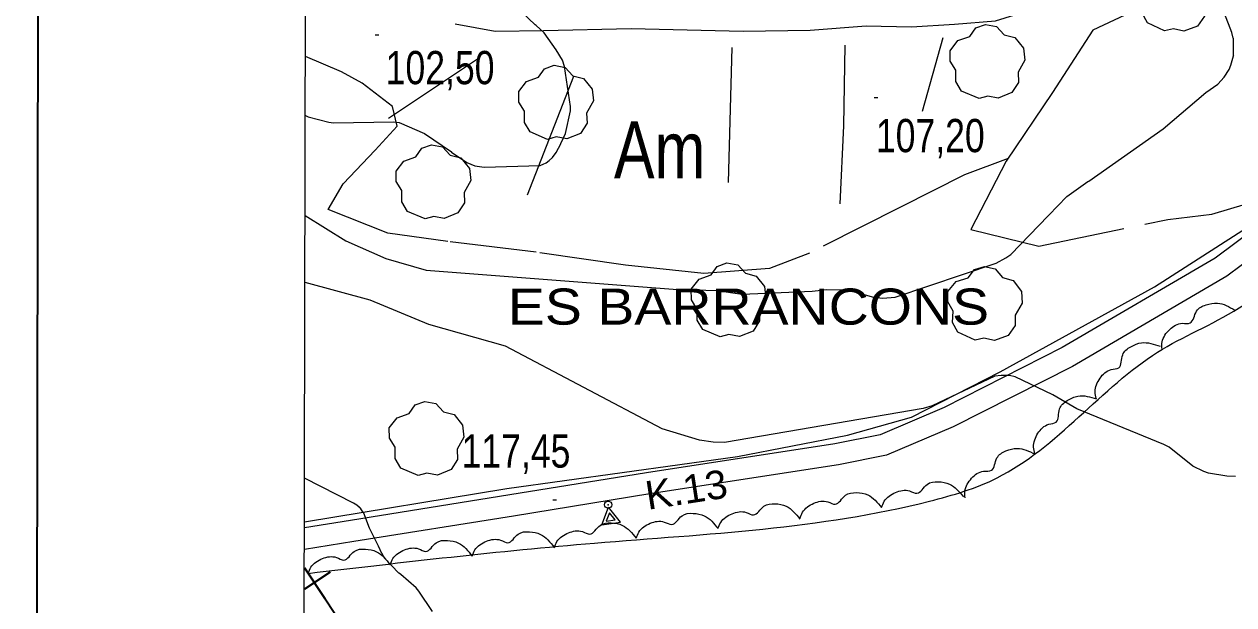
# Model space of a CAD drawing. Extents: x 483843 to 488449, y 4381269 to 4384483.
# Drawn here: x 484025.5 to 484343.7, y 4383510 to 4383662.8 of the extents above; entities that cross this region are included whole.
import ezdxf
from ezdxf.enums import TextEntityAlignment as Align

# ---------------------------------------------------------------- set-up
doc = ezdxf.new("R2010")
doc.units = 0
doc.header["$LTSCALE"] = 3.8
doc.header["$PDMODE"] = 32
doc.header["$PDSIZE"] = 1.9
doc.linetypes.add('LONG_DASHED', pattern=[7.5, 6, -1.5])
for name, color, linetype, lineweight in [('1', 7, 'Continuous', 13), ('25', 7, 'LONG_DASHED', 25), ('27', 7, 'Continuous', 25), ('29', 7, 'Continuous', 13), ('34', 7, 'Continuous', 35), ('36', 7, 'Continuous', 25), ('38', 7, 'Continuous', 25), ('41', 7, 'Continuous', 13), ('51', 7, 'Continuous', 13), ('7', 7, 'Continuous', 13), ('9', 7, 'Continuous', 13)]:
    doc.layers.add(name, color=color, linetype=linetype, lineweight=lineweight)
doc.layers.add('31', color=7, linetype='Continuous')
doc.layers.add('5', color=7, linetype='Continuous')

msp = doc.modelspace()

# ---------------------------------------------------------------- linework, layer by layer
at = {"layer": '1', "lineweight": 35}
msp.add_lwpolyline([(484030.2, 4384207.38), (487748.7, 4384200.21), (487743.96, 4381745.22), (484025.46, 4381752.39)], close=True, dxfattribs=at)
at = {"layer": '1'}
msp.add_lwpolyline([(484100.5, 4384135.8), (487678, 4384129), (487674.1, 4381816.7), (484095.6, 4381823.6)], close=True, dxfattribs=at)
at = {"layer": '25'}
for points in [[(484274.54, 4383608.75), (484292.45, 4383604.39), (484326.41, 4383611.41), (484337.99, 4383612.75), (484347.07, 4383615.48), (484354, 4383620.65), (484359.61, 4383632.36), (484364.31, 4383647.45), (484367.45, 4383659.95), (484366.16, 4383665.4), (484359.29, 4383669.31), (484346.08, 4383669.6), (484334.83, 4383667.88), (484324.29, 4383666.16), (484315.1, 4383665.12), (484306.65, 4383661.22)], [(484284.35, 4383627.47), (484272.84, 4383623.15), (484256.06, 4383614.67), (484232.1, 4383602.56), (484221.61, 4383598.5), (484204.26, 4383597.15), (484183.7, 4383599.37), (484160.17, 4383602.77), (484136.93, 4383605.6), (484121.15, 4383607.8), (484105.46, 4383613.98), (484109.42, 4383620.81), (484117.79, 4383629.65), (484123.6, 4383635.9), (484122.4, 4383641.14), (484114.42, 4383647.28), (484108.94, 4383650.21), (484099.48, 4383654.25)]]:
    msp.add_lwpolyline(points, dxfattribs=at)
at = {"layer": '27'}
for points in [[(484100.18, 4383518.27), (484175.5, 4383526.23), (484263.69, 4383537.26), (484281.44, 4383543.39), (484323.7, 4383576.47), (484345.13, 4383588.11), (484350.64, 4383590.56), (484356.77, 4383588.11), (484365.95, 4383583.21), (484390.45, 4383569.12), (484418, 4383565.44), (484471.89, 4383563.61), (484483.53, 4383561.15), (484486.59, 4383558.7), (484487.81, 4383552.58), (484489.04, 4383543.39), (484498.22, 4383540.32), (484509.86, 4383540.94), (484512.92, 4383542.78), (484541.7, 4383559.93), (484579.67, 4383560.54), (484661.11, 4383555.64), (484694.18, 4383552.58), (484705.2, 4383543.39), (484711.33, 4383534.2), (484721.74, 4383509.08), (484724.19, 4383493.76), (484729.7, 4383491.31), (484743.17, 4383488.25), (484756.03, 4383490.09)], [(484324.81, 4383577.44), (484324.9, 4383579.21), (484326.88, 4383582.44), (484330.2, 4383584.06), (484332.25, 4383584.16), (484333.95, 4383587.28), (484336.44, 4383588.92), (484339.43, 4383589.39), (484344.03, 4383587.52)], [(484307.52, 4383564.31), (484307.25, 4383566.07), (484308.55, 4383569.63), (484311.48, 4383571.88), (484313.47, 4383572.38), (484314.51, 4383575.78), (484316.62, 4383577.89), (484319.46, 4383578.94), (484324.34, 4383578.03)], [(484291.42, 4383549.76), (484291.07, 4383551.5), (484292.21, 4383555.12), (484295.03, 4383557.5), (484297, 4383558.09), (484297.89, 4383561.53), (484299.91, 4383563.73), (484302.69, 4383564.91), (484307.61, 4383564.21)], [(484273.05, 4383538.14), (484273.01, 4383539.91), (484274.74, 4383543.29), (484277.92, 4383545.15), (484279.96, 4383545.4), (484281.42, 4383548.64), (484283.78, 4383550.47), (484286.73, 4383551.16), (484291.45, 4383549.65)], [(484251.08, 4383535.58), (484251.77, 4383537.22), (484254.75, 4383539.57), (484258.42, 4383539.95), (484260.38, 4383539.33), (484263.05, 4383541.67), (484265.96, 4383542.36), (484268.92, 4383541.77), (484272.59, 4383538.43)], [(484229.57, 4383532.72), (484230.26, 4383534.35), (484233.24, 4383536.71), (484236.91, 4383537.09), (484238.87, 4383536.47), (484241.54, 4383538.81), (484244.45, 4383539.5), (484247.41, 4383538.91), (484251.08, 4383535.57)], [(484746.07, 4383463.39), (484731.66, 4383466.23), (484710.02, 4383482.88), (484695.11, 4383499.3), (484677.67, 4383512.8), (484658.52, 4383521.38), (484639.72, 4383529.93), (484613.7, 4383532.52), (484586.23, 4383535), (484560.15, 4383534.96), (484534.42, 4383531.45), (484512.75, 4383525.74), (484483.15, 4383513.44), (484467.12, 4383503.74), (484451.7, 4383489.36), (484436.59, 4383474.55), (484422.24, 4383456.04), (484409.9, 4383439.95), (484397.9, 4383426.91), (484376.97, 4383409.36), (484364.26, 4383397.36), (484342.02, 4383394.45), (484320.75, 4383398.94), (484298.45, 4383413.96), (484280.25, 4383425.55), (484249, 4383445.78), (484235.85, 4383460.09), (484215.96, 4383472.77), (484198.91, 4383469.03), (484171.82, 4383453.81), (484146.49, 4383453.37), (484110.53, 4383453.53), (484099.05, 4383450.9)], [(484186.49, 4383527.52), (484187.2, 4383529.14), (484190.21, 4383531.45), (484193.89, 4383531.77), (484195.84, 4383531.12), (484198.55, 4383533.42), (484201.47, 4383534.06), (484204.42, 4383533.42), (484208.04, 4383530.03)], [(484208.04, 4383530.04), (484208.75, 4383531.66), (484211.77, 4383533.97), (484215.44, 4383534.29), (484217.39, 4383533.64), (484220.1, 4383535.94), (484223.02, 4383536.59), (484225.97, 4383535.94), (484229.59, 4383532.55)], [(484164.93, 4383524.99), (484165.65, 4383526.62), (484168.66, 4383528.92), (484172.34, 4383529.24), (484174.29, 4383528.6), (484177, 4383530.9), (484179.91, 4383531.54), (484182.87, 4383530.9), (484186.49, 4383527.51)], [(484143.34, 4383522.83), (484144.07, 4383524.45), (484147.11, 4383526.72), (484150.79, 4383527), (484152.73, 4383526.33), (484155.47, 4383528.6), (484158.39, 4383529.21), (484161.34, 4383528.53), (484164.92, 4383525.1)], [(484100.18, 4383518.27), (484100.91, 4383519.89), (484103.95, 4383522.16), (484107.63, 4383522.44), (484109.57, 4383521.77), (484112.31, 4383524.04), (484115.23, 4383524.65), (484118.18, 4383523.97), (484121.76, 4383520.54)], [(484121.76, 4383520.55), (484122.49, 4383522.17), (484125.53, 4383524.44), (484129.21, 4383524.72), (484131.15, 4383524.05), (484133.89, 4383526.32), (484136.81, 4383526.93), (484139.76, 4383526.25), (484143.34, 4383522.82)]]:
    msp.add_spline(points, degree=3, dxfattribs=at)
at = {"layer": '29'}
for points in [[(484325.55, 4383661), (484321.01, 4383663.12), (484319.6, 4383665.66), (484319.7, 4383668.64), (484318.33, 4383671.05), (484318.37, 4383673.8), (484320.53, 4383676.4), (484323.72, 4383677.4), (484325.37, 4383679.59), (484327.94, 4383680.42), (484330.8, 4383679.77), (484332.75, 4383677.5), (484335.56, 4383676.68), (484337.69, 4383673.83), (484337.93, 4383670.7), (484336.05, 4383667.55), (484336.05, 4383664.87), (484334.23, 4383662.26), (484330.61, 4383660.92), (484327.84, 4383661.55)], [(484276.71, 4383643.22), (484272.1, 4383645.19), (484270.6, 4383647.67), (484270.59, 4383650.66), (484269.14, 4383653.02), (484269.08, 4383655.77), (484271.15, 4383658.44), (484274.31, 4383659.55), (484275.88, 4383661.8), (484278.42, 4383662.72), (484281.3, 4383662.17), (484283.33, 4383659.97), (484286.16, 4383659.24), (484288.39, 4383656.47), (484288.74, 4383653.35), (484286.97, 4383650.14), (484287.07, 4383647.46), (484285.34, 4383644.79), (484281.77, 4383643.32), (484278.98, 4383643.85)], [(484163.2, 4383632.47), (484158.59, 4383634.44), (484157.09, 4383636.92), (484157.08, 4383639.91), (484155.63, 4383642.27), (484155.57, 4383645.02), (484157.64, 4383647.69), (484160.8, 4383648.8), (484162.37, 4383651.05), (484164.91, 4383651.97), (484167.79, 4383651.42), (484169.82, 4383649.22), (484172.65, 4383648.49), (484174.88, 4383645.72), (484175.23, 4383642.6), (484173.46, 4383639.39), (484173.56, 4383636.71), (484171.83, 4383634.04), (484168.26, 4383632.57), (484165.47, 4383633.1)], [(484130.94, 4383611.55), (484126.33, 4383613.52), (484124.83, 4383616), (484124.82, 4383618.99), (484123.37, 4383621.35), (484123.31, 4383624.1), (484125.38, 4383626.77), (484128.54, 4383627.88), (484130.11, 4383630.13), (484132.65, 4383631.05), (484135.53, 4383630.5), (484137.56, 4383628.3), (484140.39, 4383627.57), (484142.62, 4383624.8), (484142.97, 4383621.68), (484141.2, 4383618.47), (484141.3, 4383615.79), (484139.57, 4383613.12), (484136, 4383611.65), (484133.21, 4383612.18)], [(484208.61, 4383580.47), (484204, 4383582.44), (484202.5, 4383584.92), (484202.49, 4383587.91), (484201.04, 4383590.27), (484200.98, 4383593.02), (484203.05, 4383595.69), (484206.21, 4383596.8), (484207.78, 4383599.05), (484210.32, 4383599.97), (484213.2, 4383599.42), (484215.23, 4383597.22), (484218.06, 4383596.49), (484220.29, 4383593.72), (484220.64, 4383590.6), (484218.87, 4383587.39), (484218.97, 4383584.71), (484217.24, 4383582.04), (484213.67, 4383580.57), (484210.88, 4383581.1)], [(484275.71, 4383579.63), (484271.17, 4383581.75), (484269.76, 4383584.29), (484269.86, 4383587.27), (484268.49, 4383589.68), (484268.53, 4383592.43), (484270.69, 4383595.03), (484273.88, 4383596.03), (484275.53, 4383598.22), (484278.1, 4383599.05), (484280.96, 4383598.4), (484282.91, 4383596.13), (484285.72, 4383595.31), (484287.85, 4383592.46), (484288.09, 4383589.33), (484286.21, 4383586.18), (484286.21, 4383583.5), (484284.39, 4383580.89), (484280.77, 4383579.55), (484278, 4383580.18)], [(484129.15, 4383544.01), (484124.54, 4383545.98), (484123.04, 4383548.46), (484123.03, 4383551.45), (484121.58, 4383553.81), (484121.52, 4383556.56), (484123.59, 4383559.23), (484126.75, 4383560.34), (484128.32, 4383562.59), (484130.86, 4383563.51), (484133.74, 4383562.96), (484135.77, 4383560.76), (484138.6, 4383560.03), (484140.83, 4383557.26), (484141.18, 4383554.14), (484139.41, 4383550.93), (484139.51, 4383548.25), (484137.78, 4383545.58), (484134.21, 4383544.11), (484131.42, 4383544.64)]]:
    msp.add_lwpolyline(points, close=True, dxfattribs=at)
at = {"layer": '34'}
for p, q in [((484105.93, 4383518.61), (484099.18, 4383514.13)), ((484099.19, 4383519.71), (484104.53, 4383511.68))]:
    msp.add_line(p, q, dxfattribs=at)
msp.add_lwpolyline([(484099.19, 4383519.71), (484401, 4383066), (484435, 4383073), (484458, 4383093), (484473, 4383128), (484463, 4383264), (484450, 4383353), (484466, 4383389), (484492, 4383415), (484531, 4383430), (484588, 4383427), (484638, 4383413)], dxfattribs=at)
at = {"layer": '36'}
for points in [[(484349.52, 4383609.16), (484338.85, 4383601.2), (484298.57, 4383577.66), (484267.54, 4383561.91), (484250.72, 4383554.74), (484238.74, 4383552.37), (484189.2, 4383544.7), (484153.28, 4383538.89), (484111.35, 4383532.19), (484099.22, 4383530.22)], [(484355.45, 4383607.15), (484353.2, 4383604.9), (484341.95, 4383596.51), (484301.26, 4383572.73), (484269.92, 4383556.81), (484252.38, 4383549.34), (484239.72, 4383546.84), (484190.08, 4383539.15), (484154.17, 4383533.34), (484112.24, 4383526.64), (484099.2, 4383524.53)]]:
    msp.add_lwpolyline(points, dxfattribs=at)
at = {"layer": '38'}
msp.add_lwpolyline([(484138.9, 4383662.83), (484149.36, 4383660.96), (484162.08, 4383661.08), (484185.21, 4383661.67), (484214.63, 4383660.95), (484232.3, 4383661.2), (484247.02, 4383662.33), (484258.93, 4383662.11), (484270.22, 4383662.77), (484281.03, 4383663.69), (484295.2, 4383668.05), (484308.99, 4383674.99), (484316.46, 4383678.23), (484326.27, 4383679.07), (484332.14, 4383679.24), (484342.25, 4383680.98), (484348.42, 4383684.9)], dxfattribs=at)
at = {"layer": '41'}
for p, q in [((484177.41, 4383531.02), (484179.22, 4383535.68)), ((484182.35, 4383531.78), (484179.22, 4383535.68)), ((484177.41, 4383531.02), (484182.35, 4383531.78))]:
    msp.add_line(p, q, dxfattribs=at)
msp.add_lwpolyline([(484179.45, 4383534.2), (484178.58, 4383531.96), (484180.95, 4383532.32)], close=True, dxfattribs=at)
msp.add_point((484179.12, 4383536.34), dxfattribs=at)
at = {"layer": '51'}
for p, q in [((484261.81, 4383639.85), (484267.24, 4383659.29)), ((484211.64, 4383656.6), (484210.67, 4383621.08)), ((484144.74, 4383653.56), (484121.3, 4383637.98)), ((484157.89, 4383617.87), (484170.09, 4383649.14))]:
    msp.add_line(p, q, dxfattribs=at)
for points in [[(484099.22, 4383531.84), (484152.43, 4383540.61), (484213.14, 4383549), (484242.11, 4383554.64), (484258.94, 4383559.4), (484282.28, 4383571.32), (484322.87, 4383593.65), (484351.7, 4383612.15), (484359.02, 4383620.36), (484363.55, 4383629.89), (484370.47, 4383653.64), (484383.55, 4383699.81)], [(484306.65, 4383661.22), (484296.05, 4383644.76), (484283.88, 4383626.77), (484274.54, 4383608.75)], [(484241.43, 4383657.29), (484241.01, 4383636.05), (484240.07, 4383615.46)]]:
    msp.add_lwpolyline(points, dxfattribs=at)
at = {"layer": '7'}
for p, q in [((484117.81, 4383659.99), (484118.81, 4383659.99)), ((484249.07, 4383643.46), (484250.07, 4383643.46)), ((484164.56, 4383537.61), (484165.56, 4383537.61))]:
    msp.add_line(p, q, dxfattribs=at)
at = {"layer": '9'}
for points in [[(484099.39, 4383612.46), (484110.07, 4383605.78), (484120.59, 4383601.09), (484131.23, 4383598.06), (484196.18, 4383593.06), (484207.72, 4383592.66), (484214.37, 4383591.76), (484232.82, 4383592.5), (484236.67, 4383592.94), (484240.58, 4383592.88), (484243.69, 4383592.42), (484248.9, 4383590.93), (484251.38, 4383590.7), (484254.61, 4383590.96), (484281.25, 4383599.91), (484283.8, 4383601.28), (484285.11, 4383602.21), (484294.93, 4383612.33), (484295.05, 4383612.51), (484299.82, 4383617.39), (484305.3, 4383621.35), (484305.6, 4383621.46), (484325.15, 4383635.2), (484336.42, 4383644.78), (484339.5, 4383646.96), (484341.17, 4383648.82), (484342.49, 4383650.83), (484342.98, 4383652.02), (484343.66, 4383654.45), (484343.7, 4383654.58), (484343.71, 4383654.61), (484343.7, 4383654.61), (484343.63, 4383659.12), (484343.61, 4383659.13), (484343.2, 4383660.63), (484341.28, 4383665.56)], [(484099.45, 4383638.77), (484100.18, 4383638.42), (484105.58, 4383637.01), (484106.84, 4383636.83), (484122.68, 4383637.07), (484124.11, 4383636.87), (484130.83, 4383634.02), (484137.86, 4383629.23), (484137.88, 4383629.19), (484137.9, 4383629.17), (484137.93, 4383629.11), (484141.94, 4383626.42), (484144, 4383625.53), (484146.52, 4383625.18), (484161.2, 4383625.63), (484161.36, 4383625.66), (484162.05, 4383625.92), (484162.83, 4383626.33), (484163.63, 4383626.9), (484164.49, 4383627.72), (484165.46, 4383629.03), (484166.66, 4383631.31), (484166.66, 4383631.33), (484166.7, 4383631.36), (484167.92, 4383634.05), (484169.17, 4383639.99), (484169.2, 4383641.09), (484167.59, 4383651.62), (484167.07, 4383653.29), (484165.47, 4383656.07), (484162.28, 4383660.48), (484160.14, 4383662.46), (484159.95, 4383662.59), (484156.36, 4383665.94)], [(484344.2, 4383543.79), (484341.91, 4383543.83), (484337.1, 4383544.6), (484335.84, 4383545.03), (484332.98, 4383546.45), (484326.71, 4383551.49), (484325.36, 4383552.21), (484302.42, 4383561.57), (484296.15, 4383565.26), (484286.21, 4383569.95), (484284.71, 4383570.34), (484282.52, 4383570.35), (484280.87, 4383570.12), (484264.35, 4383562.37), (484262, 4383561.67), (484209.71, 4383552.73), (484206.75, 4383552.77), (484203.12, 4383553.3), (484193.34, 4383556.31), (484152.09, 4383578.09), (484131.89, 4383583.71), (484116.51, 4383590.16), (484099.35, 4383594.79)], [(484112.96, 4383536.21), (484112.14, 4383536.77), (484099.24, 4383543.31)], [(484132.89, 4383508.25), (484129.33, 4383513.6), (484128.57, 4383514.42), (484124.6, 4383517.97), (484124.44, 4383518.01), (484124.03, 4383518.35), (484120.15, 4383522.33), (484120.14, 4383522.35), (484120.13, 4383522.38), (484120.14, 4383522.48), (484120.08, 4383522.7), (484120.03, 4383522.8), (484119.11, 4383524.33), (484119.11, 4383524.36), (484119.11, 4383524.45), (484118.73, 4383525.44), (484116.3, 4383530.18), (484114.79, 4383534.11), (484114.65, 4383534.28), (484113.96, 4383535.41), (484113.83, 4383535.51), (484113.75, 4383535.53), (484113.71, 4383535.54), (484113.65, 4383535.58), (484112.96, 4383536.21)]]:
    msp.add_lwpolyline(points, dxfattribs=at)

# ---------------------------------------------------------------- texts
at = {"layer": '31', "width": 0.8}
msp.add_text('Am', height=15, dxfattribs=at).set_placement((484192.67, 4383622.2), align=Align.CENTER)
at = {"layer": '41', "width": 1.05}
msp.add_text('K.13', height=7.5, rotation=8.761, dxfattribs=at).set_placement((484189.54, 4383534.97))
at = {"layer": '5', "width": 1.15}
msp.add_text('ES BARRANCONS', height=9.5, dxfattribs=at).set_placement((484279.35, 4383583.71), align=Align.RIGHT)
at = {"layer": '7', "width": 0.8}
for s, p in [('102,50', (484120.58, 4383646.98)), ('107,20', (484249.57, 4383629.09)), ('117,45', (484140.55, 4383546.08))]:
    msp.add_text(s, height=8.75, dxfattribs=at).set_placement(p)

doc.saveas('drawing.dxf')
